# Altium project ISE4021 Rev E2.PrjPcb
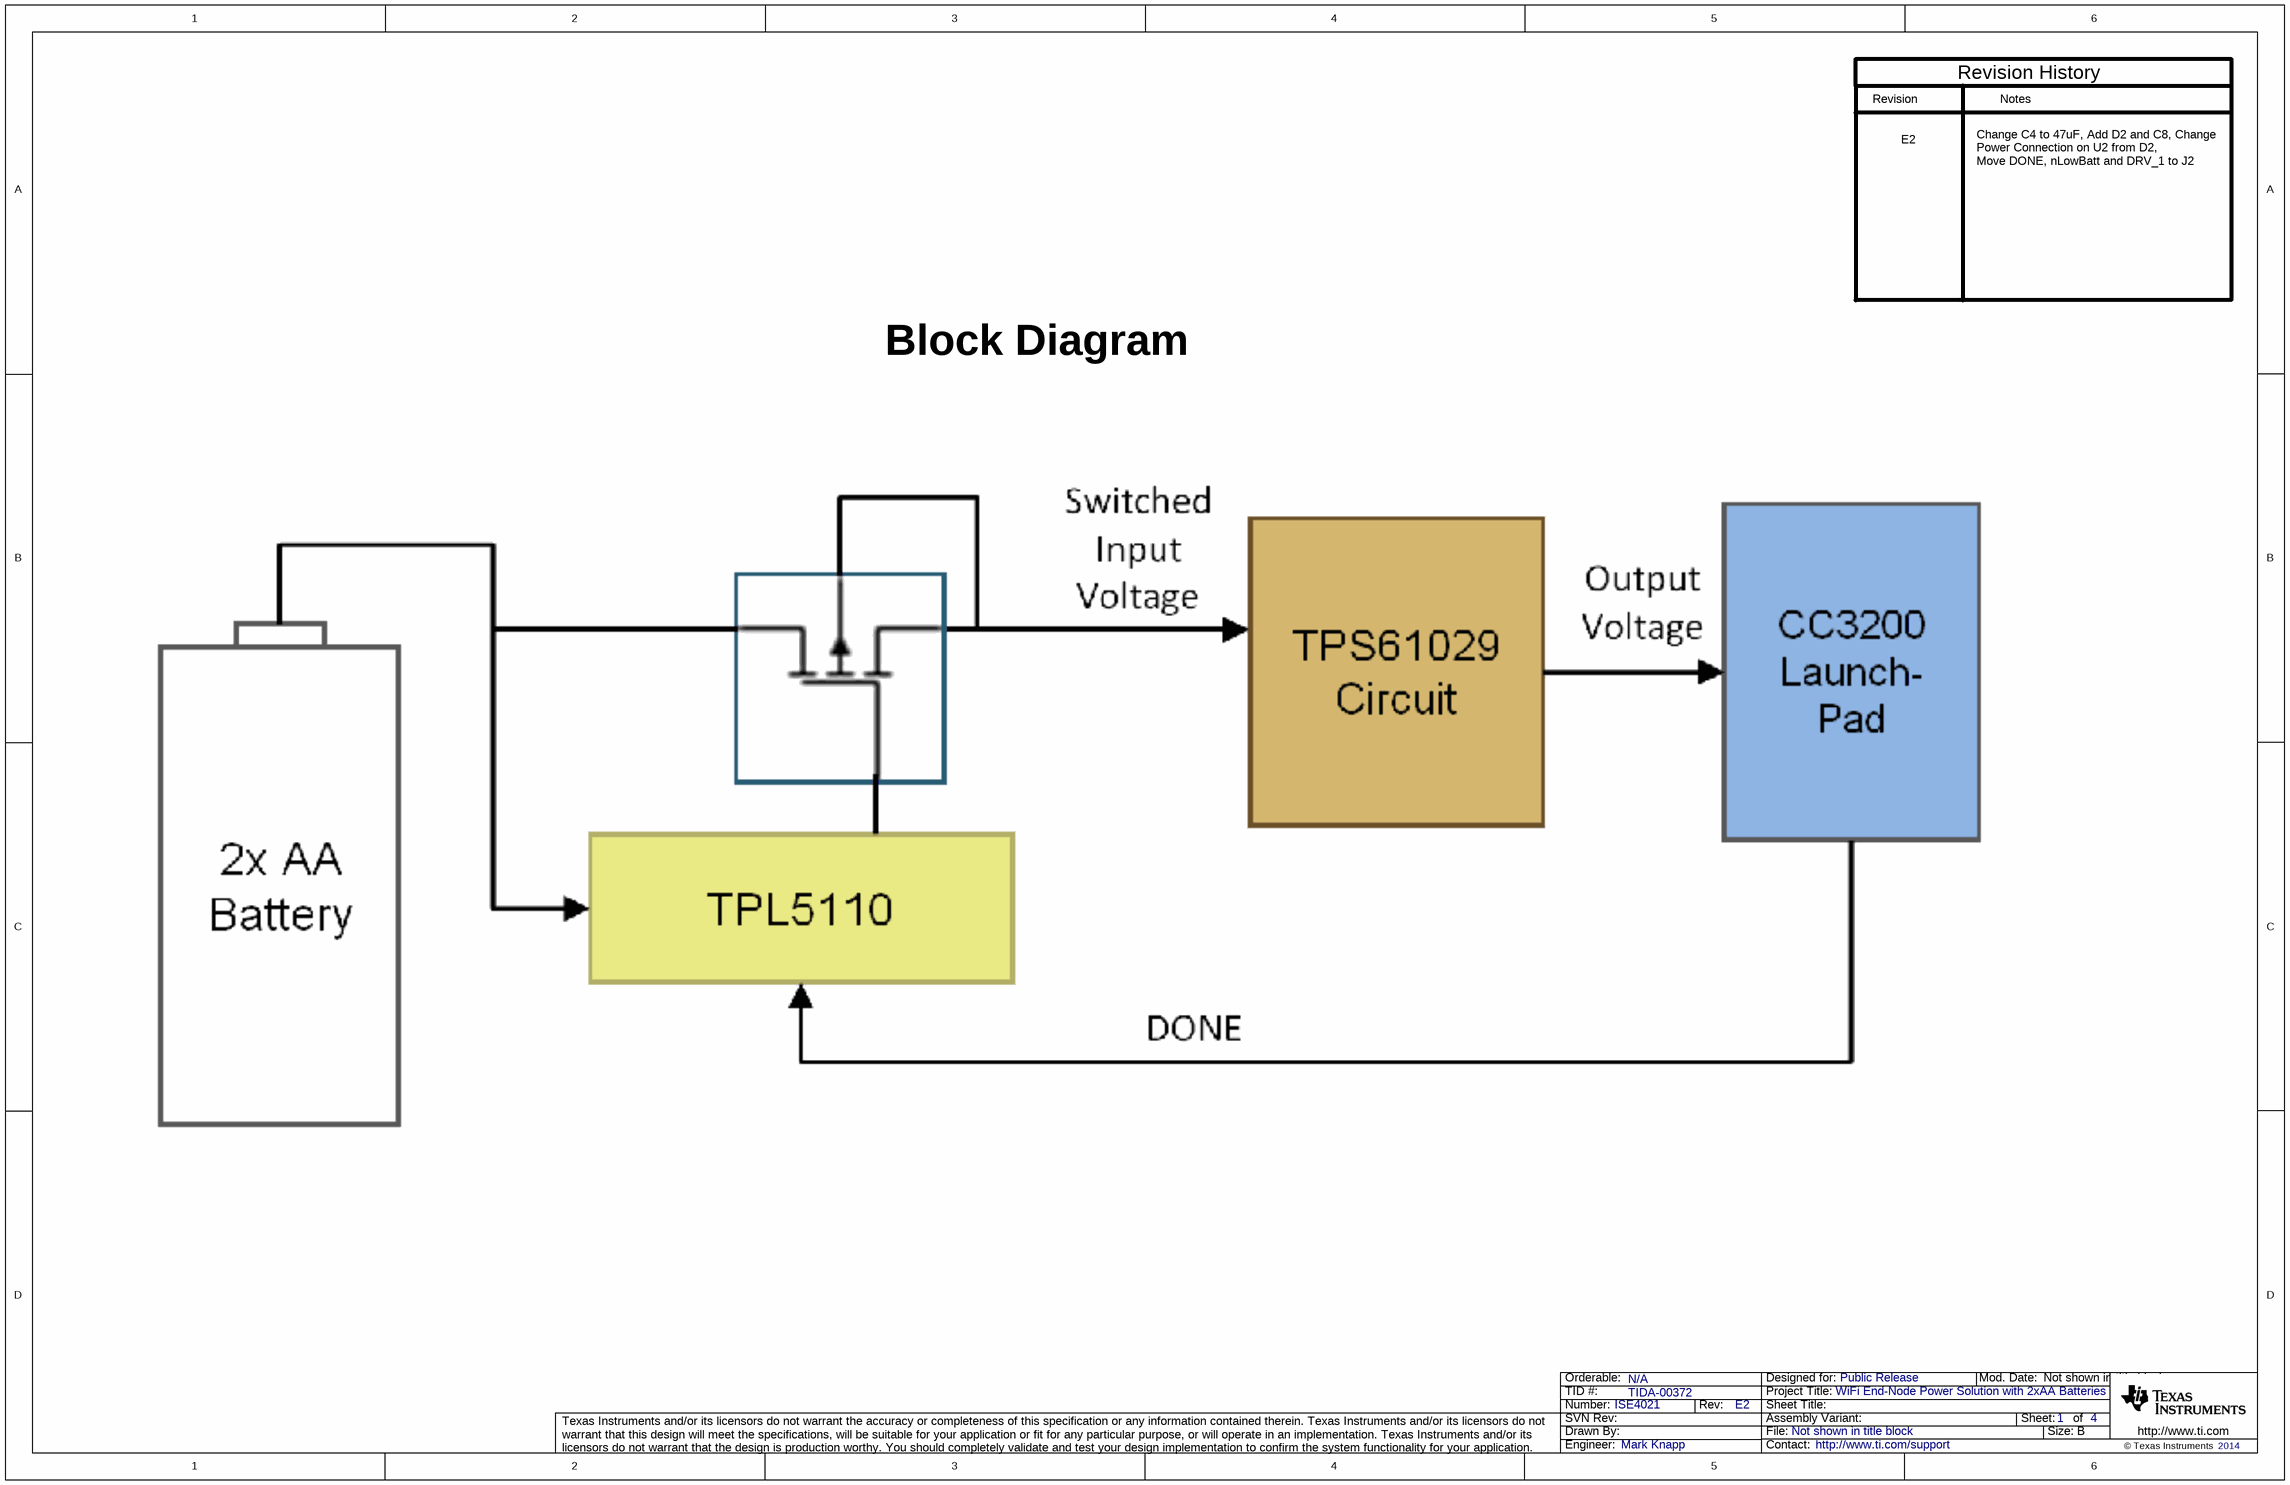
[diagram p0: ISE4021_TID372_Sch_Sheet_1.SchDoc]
TID: TIDA-00372; TechSupport: http://www.ti.com/support; SCH_Rev: E2; PRJ_Title: WiFi End-Node Power Solution with 2xAA Batteries; PRJ_Number: ISE4021; PRJ_Engineer: Mark Knapp; PRJ_Customer: Public Release; PCB_Rev: E2; PCB_Layout: Krypton Solutions LLC; EVM_Orderable: N/A; CopyrightYear: 2014
4 sheets, 58 parts. Net scope: global (net labels, ports and power ports of the same name join across sheets).
Board file: ISE4021_TID372_PCB.PcbDoc
Sheets:
  ISE4021_TID372_Sch_Sheet_1.SchDoc
  ISE4021_TID372_Sch_Sheet_2.SchDoc
  ISE4021_TID372_Sch_Sht_3.SchDoc
  ISE4021_TID372_Sch_Sheet_4.SchDoc

## Sheet ISE4021_TID372_Sch_Sheet_1.SchDoc
size 431 x 279 mm; Date: Not shown in title block; ApprovedBy: Not shown in title block; CheckedBy: Not shown in title block; Author: Not shown in title block; CompanyName: Not shown in title block; Engineer: Not shown in title block; Organization: Not shown in title block; Address1: Not shown in title block; Address2: Not shown in title block; Address3: Not shown in title block; Address4: Not shown in title block; DocumentNumber: 1; Revision: Use project parameter SCH_Rev; SheetNumber: 1; SheetTotal: 4; PageSetup: Record=PageOptions¦CenterHorizontal=True¦CenterVertical=True¦PrintScale=1.00¦XCorrection=1.00¦YCorrection=1.00¦PrintKind=0¦BorderSize=5000000¦LeftOffset=0¦BottomOffset=0¦Orientation=2¦PaperLength=1000¦PaperWidth=1000¦Scale=100¦PaperSource=15¦PrintQuality=600¦MediaType=1¦DitherType=10¦PaperKind=Letter¦PrintScaleMode=1

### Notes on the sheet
- Revision
- Notes
- Revision History
- E2
- Change C4 to 47uF, Add D2 and C8, Change Power Connection on U2 from D2,
  Move DONE, nLowBatt and DRV_1 to J2
- Block Diagram

## Sheet ISE4021_TID372_Sch_Sheet_2.SchDoc
size 431 x 279 mm; Date: Not shown in title block; ApprovedBy: Not shown in title block; CheckedBy: Not shown in title block; Author: Not shown in title block; CompanyName: Not shown in title block; Engineer: Not shown in title block; Organization: Not shown in title block; Address1: Not shown in title block; Address2: Not shown in title block; Address3: Not shown in title block; Address4: Not shown in title block; DocumentNumber: 2; Revision: Use project parameter SCH_Rev; SheetNumber: 2; SheetTotal: 4; PageSetup: Record=PageOptions¦CenterHorizontal=True¦CenterVertical=True¦PrintScale=0.96¦XCorrection=1.00¦YCorrection=1.00¦PrintKind=0¦BorderSize=5000000¦LeftOffset=0¦BottomOffset=0¦Orientation=2¦PaperLength=4318¦PaperWidth=2794¦Scale=100¦PaperSource=15¦PrintQuality=600¦MediaType=1¦DitherType=10¦PrintScaleMode=1¦PaperKind=Tabloid (11 x 17")¦PaperIndex=17
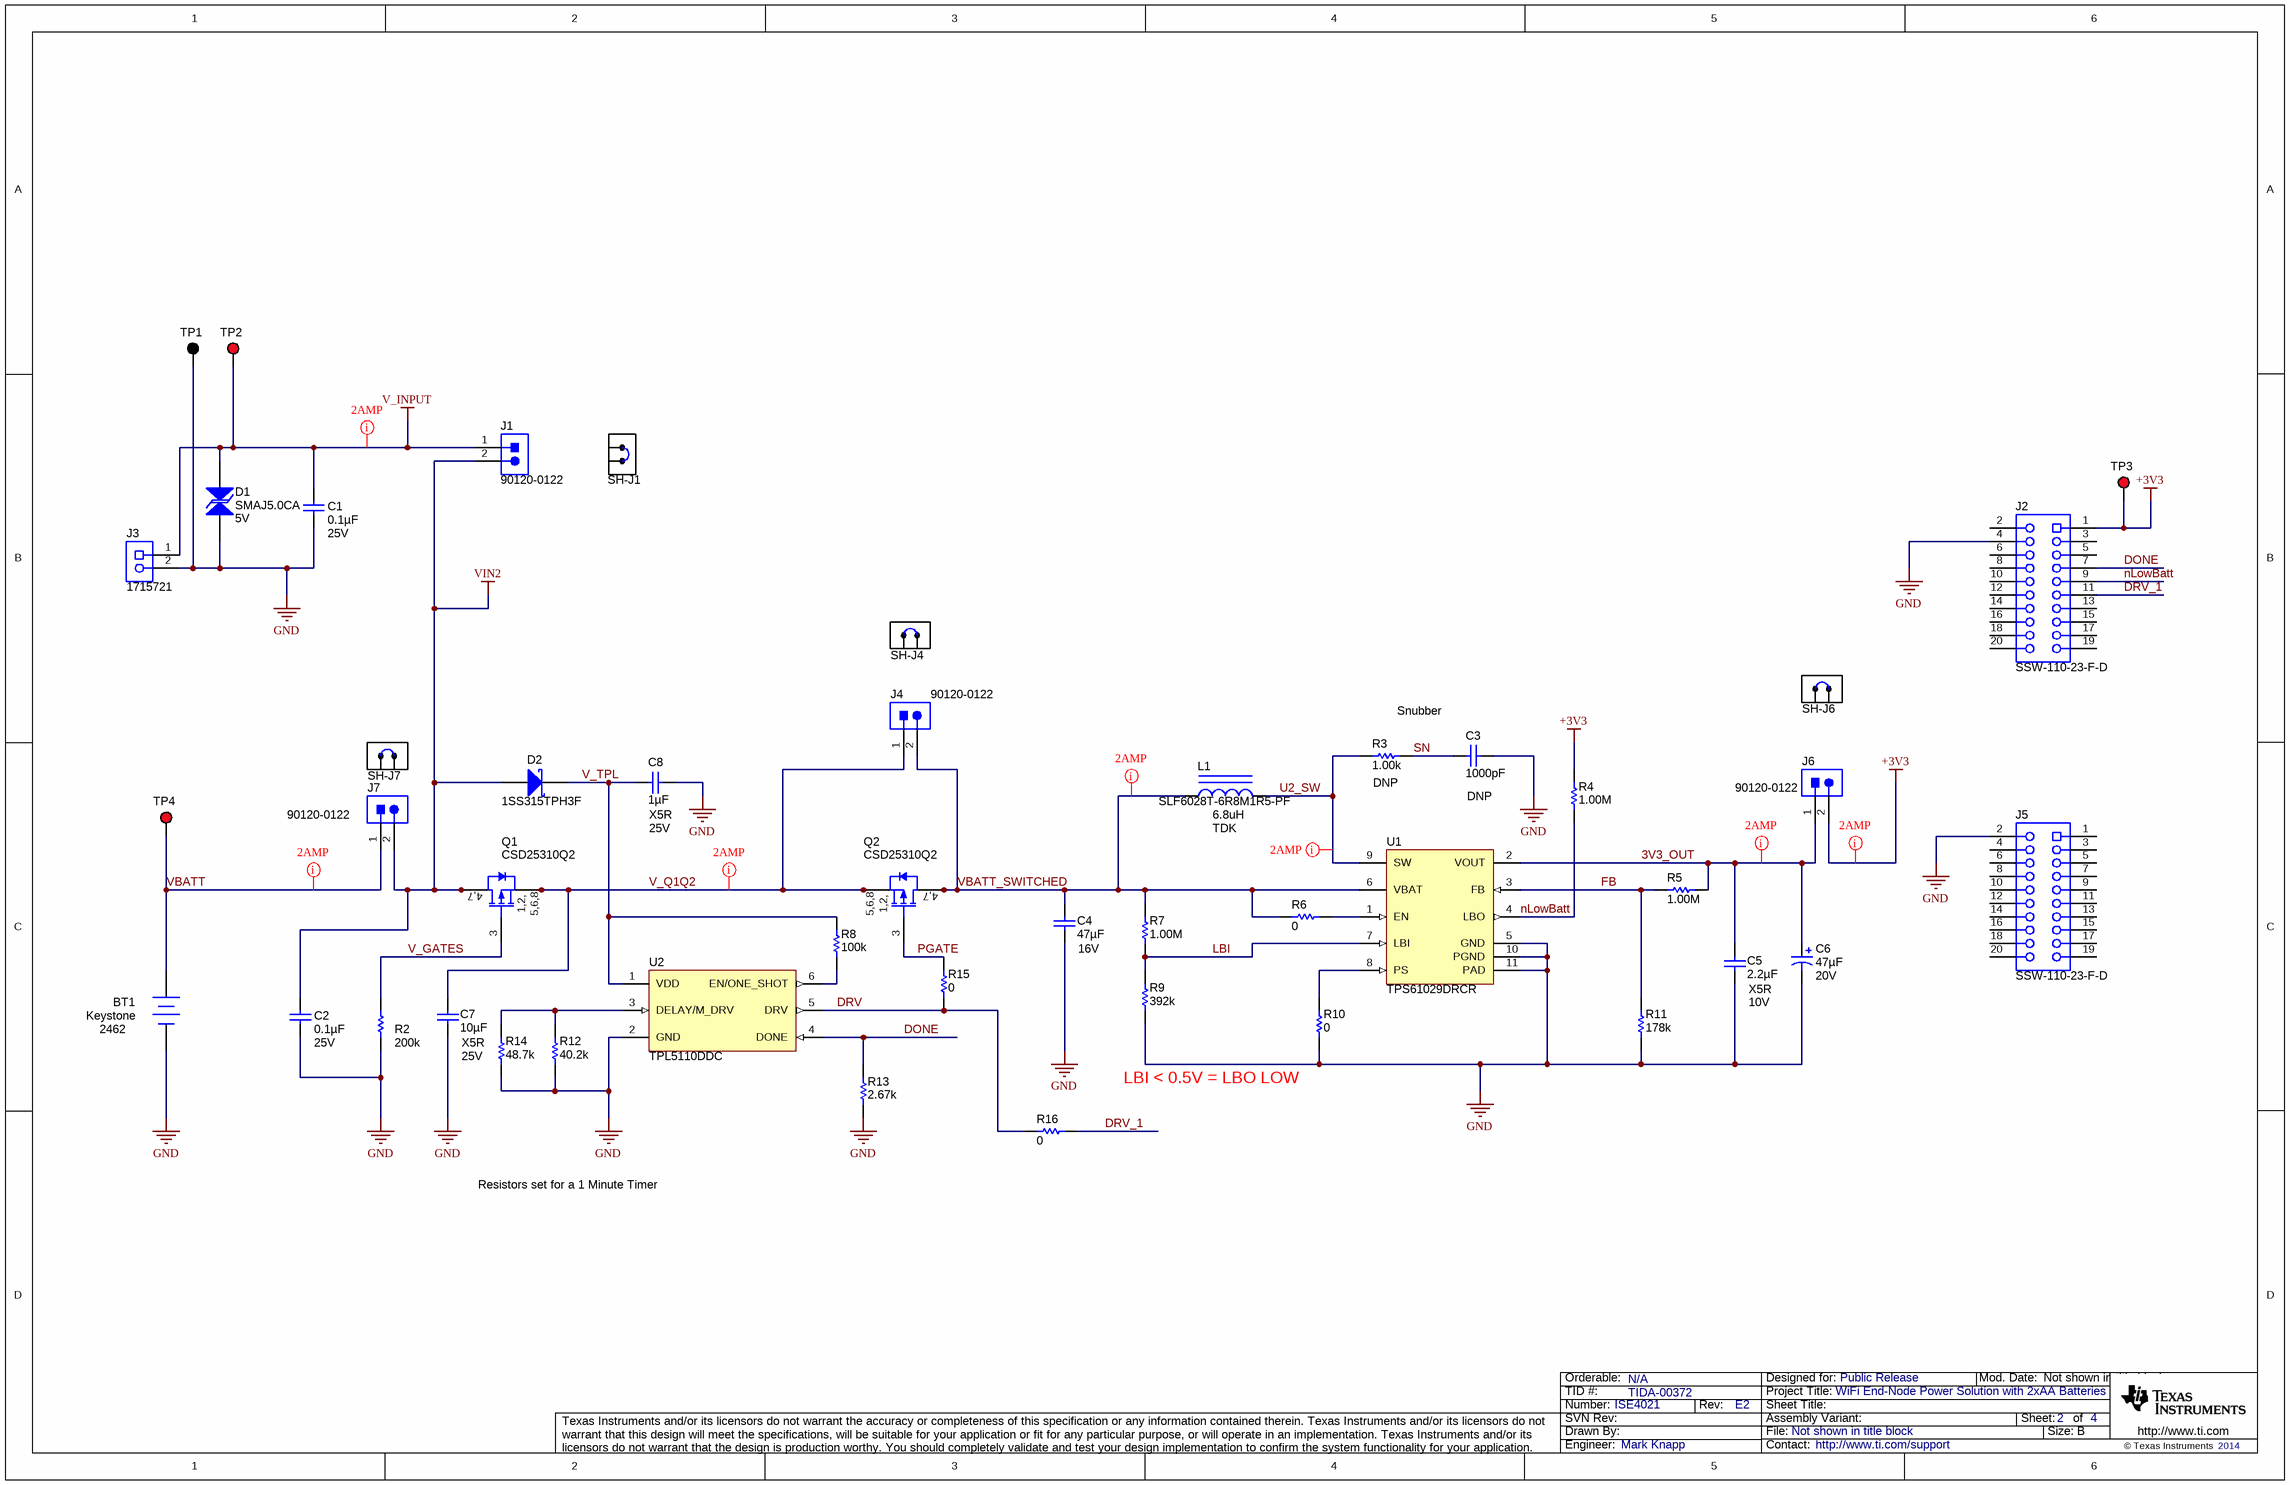
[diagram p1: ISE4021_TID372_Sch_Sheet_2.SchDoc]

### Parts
BT1  Manufacturer: Keystone  [Keystone_2462]  (hidden comment: 2462)
C1  ValueDisplayed: 0.1µF  Value2: 25V  [0603]  (hidden comment: 06033C104JAT2A)
C2  ValueDisplayed: 0.1µF  Value2: 25V  [0603]  (hidden comment: 06033C104JAT2A)
C3  ValueDisplayed: 1000pF  [0402]  (hidden comment: C1005C0G1E102J)
C4  ValueDisplayed: 47µF  Value2: 16V  [1210]  (hidden comment: GRM32ER61C476KE15L)
C5  ValueDisplayed: 2.2µF  Value2: 10V  TempCo: X5R  [0805_HV]  (hidden comment: C2012X5R1A225K/0.85)
C6  ValueDisplayed: 47µF  Value2: 20V  [7343-31]  (hidden comment: T495D476K020ATE100)
C7  ValueDisplayed: 10µF  Value2: 25V  TempCo: X5R  [0805_HV]  (hidden comment: C2012X5R1E106K125AB)
C8  ValueDisplayed: 1µF  Value2: 25V  TempCo: X5R  [0805_HV]  (hidden comment: GRM216R61E105KA12D)
D1  SMAJ5.0CA  value 5V  [SMA]
D2  1SS315TPH3F  [sod-323]
J1  90120-0122  [CONN_90120-0122]
J2  SSW-110-23-F-D  [CONN_SSW-110-23-F-D]
J3  1715721  [PhoenixContact_1715721]
J4  90120-0122  [CONN_90120-0122]
J5  SSW-110-23-F-D  [CONN_SSW-110-23-F-D]
J6  90120-0122  [CONN_90120-0122]
J7  90120-0122  [CONN_90120-0122]
L1  SLF6028T-6R8M1R5-PF  value 6.8uH  Manufacturer: TDK  [SLF6028]
Q1  CSD25310Q2  [TRANS_NexFET_Q2]
Q2  CSD25310Q2  [TRANS_NexFET_Q2]
R2  ValueDisplayed: 200k  [0402]  (hidden comment: CRCW0402200KFKED)
R3  ValueDisplayed: 1.00k  [0402]  (hidden comment: CRCW04021K00FKED)
R4  ValueDisplayed: 1.00M  [0603]  (hidden comment: CRCW06031M00FKEA)
R5  ValueDisplayed: 1.00M  [0603]  (hidden comment: CRCW06031M00FKEA)
R6  ValueDisplayed: 0  [0603]  (hidden comment: CRCW06030000Z0EA)
R7  ValueDisplayed: 1.00M  [0603]  (hidden comment: CRCW06031M00FKEA)
R8  ValueDisplayed: 100k  [0603]  (hidden comment: CRCW0603100KFKEA)
R9  ValueDisplayed: 392k  [0603]  (hidden comment: CRCW0603392KFKEA)
R10  ValueDisplayed: 0  [0603]  (hidden comment: CRCW06030000Z0EA)
R11  ValueDisplayed: 178k  [0603]  (hidden comment: CRCW0603178KFKEA)
R12  ValueDisplayed: 40.2k  [0603]  (hidden comment: CRCW060340K2FKEA)
R13  ValueDisplayed: 2.67k  [0603]  (hidden comment: CRCW06032K67FKEA)
R14  ValueDisplayed: 48.7k  [0603]  (hidden comment: CRCW060348K7FKEA)
R15  ValueDisplayed: 0  [0402]  (hidden comment: CRCW04020000Z0ED)
R16  ValueDisplayed: 0  [0402]  (hidden comment: CRCW04020000Z0ED)
SH-J1  2SN-BK-G  [2SN-BK-G]  (value not drawn)
SH-J4  2SN-BK-G  [2SN-BK-G]  (value not drawn)
SH-J6  2SN-BK-G  [2SN-BK-G]  (value not drawn)
SH-J7  2SN-BK-G  [2SN-BK-G]  (value not drawn)
TP1  5001  [Keystone5001]  (value not drawn)
TP2  5000  [Keystone5000]  (value not drawn)
TP3  5000  [Keystone5000]  (value not drawn)
TP4  5000  [Keystone5000]  (value not drawn)
U1  TPS61029DRCR  [DRC0010A]
U2  TPL5110DDC  [DDC0006A_N]

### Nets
+3V3: J2.1 J6.2 R4.2 TP3.1
GND: BT1.2(-) C1.2 C2.2 C3.2 C4.2 C5.2 C6.2(-) C7.2 C8.1 D1.2 J2.4 J3.2 J5.2 R2.1 R9.1 R10.1 R11.1 R12.1 R13.1 R14.1 TP1.1 U1.5(GND) U1.10(PGND) U1.11(PAD) U2.2(GND)
V_INPUT: C1.1 D1.1 J1.1 J3.1 TP2.1
VIN2: C2.1 D2.2(A) J1.2 J7.2 Q1.4(D) Q1.7(D)
3V3_OUT: C5.1 C6.1(+) J6.1 R5.2 U1.2(VOUT)
DONE: J2.7 R13.2 U2.4(DONE)
DRV: R15.1 R16.2 U2.5(DRV)
DRV_1: J2.11 R16.1
FB: R5.1 R11.2 U1.3(FB)
LBI: R7.1 R9.2 U1.7(LBI)
nLowBatt: J2.9 R4.1 U1.4(LBO)
PGATE: Q2.3(G) R15.2
SN: C3.1 R3.1
U2_SW: L1.2 R3.2 U1.9(SW)
V_GATES: Q1.3(G) R2.2
V_Q1Q2: C7.1 J4.1 Q1.1(S) Q1.2(S) Q1.5(S) Q1.6(S) Q1.8(S) Q2.1(S) Q2.2(S) Q2.5(S) Q2.6(S) Q2.8(S)
V_TPL: C8.2 D2.1(K) R8.2 U2.1(VDD)
VBATT: BT1.1(+) J7.1 TP4.1
VBATT_SWITCHED: C4.1 J4.2 L1.1 Q2.4(D) Q2.7(D) R6.1 R7.2 U1.6(VBAT)
NetR6_2: R6.2 U1.1(EN)
NetR8_1: R8.1 U2.6(EN/ONE_SHOT)
NetR10_2: R10.2 U1.8(PS)
NetR12_2: R12.2 R14.2 U2.3(DELAY/M_DRV)

Not connected (* = marked no-connect by the designer): J2 2 3 5 6 8 10 12 13 14 15 16 17 18 19 20; J5 1 3 4 5 6 7 8 9 10 11 12 13 14 15 16 17 18 19 20

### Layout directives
2AMP: 2AMP: 3V3_OUT, +3V3, U2_SW, V_INPUT, V_Q1Q2, VBATT, VBATT_SWITCHED

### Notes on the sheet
- Snubber
- (near R3) DNP
- (near C3) DNP
- LBI < 0.5V = LBO LOW
- Resistors set for a 1 Minute Timer

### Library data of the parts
BT1 = 2462: 2x AA Battery Holder, Through-hole mount
C1 C2 = 06033C104JAT2A: CAP, CERM, 0.1 µF, 25 V, +/- 5%, X7R, 0603; Manufacturer: AVX; Polarized: N; CompType: Capacitor; Value: 0.1uF; U/M: EA; Cap_F: 0.0000001; Tolerance_%: 5; ESR_ohm: 0.05; Value1: 0.05 ohm; VDC_V: 25; TaMin_C: -55; TaMax_C: 125
C3 = C1005C0G1E102J: CAP, CERM, 1000 pF, 25 V, +/- 5%, C0G/NP0, 0402; Manufacturer: TDK; Polarized: N; CompType: Capacitor; Value: 1000pF; U/M: EA; Cap_F: 0.000000001; Tolerance_%: 5; Value1: Unknown; VDC_V: 25; Value2: 25V; TaMin_C: -55; TaMax_C: 125
C4 = GRM32ER61C476KE15L: CAP, CERM, 47 µF, 16 V, +/- 10%, X5R, 1210; Manufacturer: MuRata; Polarized: N; CompType: Capacitor; Value: 47uF; U/M: EA; Cap_F: 0.000047; Tolerance_%: 10; Value1: Unknown; VDC_V: 16; TaMin_C: -55; TaMax_C: 85
C5 = C2012X5R1A225K/0.85: CAP, CERM, 2.2 µF, 10 V, +/- 10%, X5R, 0805; Manufacturer: TDK; Polarized: N; CompType: Capacitor; Value: 2.2uF; U/M: EA; Cap_F: 0.0000022; Tolerance_%: 10; ESR_ohm: 0.0049; Value1: 0.0049 ohm; IRMS_A: 2.08; TaMin_C: -55; TaMax_C: 85; Cap_Case: 0805
C6 = T495D476K020ATE100: CAP, TA, 47 µF, 20 V, +/- 10%, 0.1 ohm, SMD; Manufacturer: Kemet; Polarized: Y; CompType: Capacitor; Value: 47uF; U/M: EA; Cap_F: 0.000047; Tolerance_%: 10; Value1: 0.1 ohm; VDC_V: 20; ESR_ohm: 0.1; IRMS_A: 1.102; TaMin_C: -55; TaMax_C: 125; Cap_Case: D
C7 = C2012X5R1E106K125AB: CAP, CERM, 10 µF, 25 V, +/- 10%, X5R, 0805; Manufacturer: TDK; Polarized: N; CompType: Capacitor; Value: 10uF; U/M: EA; Cap_F: 0.00001; Tolerance_%: 10; Value1: Unknown; VDC_V: 25; TaMin_C: -55; TaMax_C: 85; Cap_Case: 0805
C8 = GRM216R61E105KA12D: CAP, CERM, 1 µF, 25 V, +/- 10%, X5R, 0805; Manufacturer: MuRata; Polarized: N; CompType: Capacitor; Value: 1uF; U/M: EA; Cap_F: 0.000001; Tolerance_%: 10; ESR_ohm: 0.009; Value1: 0.009 ohm; VDC_V: 25; TaMin_C: -55; TaMax_C: 85; Cap_Case: 0805
D1 = SMAJ5.0CA: Diode, TVS, Bi, 5 V, 400 W, SMA; Manufacturer: Littelfuse; U/M: EA; Power_W: 400; Vr_V: 5; Value1: 400W; RJA_CperW: 120
D2 = 1SS315TPH3F: Diode, Schottky, 5 V, 0.03 A, SOD-323; Manufacturer: Toshiba; U/M: EA; Vf_V: 0.38; Value: 5V; Value1: 0.03A; Value2: 0.38V; Io_A: 0.03; Vr_V: 5; TJmax_C: 125
J1 J4 J6 J7 = 90120-0122: Header, 100mil, 2x1, Tin, TH; Manufacturer: Molex; SymbolCreator: a0412235; U/M: EA
J2 J5 = SSW-110-23-F-D: Connector, Receptacle, 100mil, 10x2, Gold plated, TH; Manufacturer: Samtec; SymbolCreator: a0412235; U/M: EA
J3 = 1715721: Conn Term Block, 2POS, 5.08mm, TH; Manufacturer: Phoenix Contact; SymbolCreator: a0412235; Value: 2x1; CompType: Terminal Block; U/M: EA
L1 = SLF6028T-6R8M1R5-PF: Inductor, Shielded Drum Core, Ferrite, 6.8 µH, 1.5 A, 0.0354 ohm, SMD; Ind_H: 6.8E-6; ValueDisplayed: 6.8µH; Imax_A: 1.5; Irms: 2.2A @ 25C rise; Isat: 1.5A @ 30% inductance drop; DCR_ohm: 0.0354; Value2: 1.5A
Q1 Q2 = CSD25310Q2: MOSFET, P-CH, -20 V, -20 A, SON 2x2mm; Manufacturer: Texas Instruments; Alternate Manufacturer: None; SymbolCreator: a0411947; U/M: EA; ChType: P; Value: -20V; Value1: 0.0239 ohm; Rdson45_ohm: 0.0239; Value2: 3.6 nC; QgTyp_nC: 3.6; Vgs_V: 8
R2 = CRCW0402200KFKED: RES, 200 k, 1%, 0.063 W, 0402; Manufacturer: Vishay-Dale; CompType: Resistor; Res_ohm: 200000; Value: 200k; Tolerance_%: 1; Power_W: 0.063; Value2: 0.063W; VDC_V: 50; TempCo: 100 ppm/C; EIA_Code: E96; U/M: EA
R3 = CRCW04021K00FKED: RES, 1.00 k, 1%, 0.063 W, 0402; Manufacturer: Vishay-Dale; CompType: Resistor; Value: 1.00k; Res_ohm: 1000; Value_Code: 1k00; Tolerance_%: 1; Power_W: 0.063; Value2: 0.063W; VDC_V: 50; TempCo: 100 ppm/C; EIA_Code: E96; U/M: EA
R4 R5 R7 = CRCW06031M00FKEA: RES, 1.00 M, 1%, 0.1 W, 0603; Manufacturer: Vishay-Dale; CompType: Resistor; Value: 1.00Meg; Res_ohm: 1000000; Value_Code: 1M00; Tolerance_%: 1; Power_W: 0.1; Value2: 0.1W; VDC_V: 75; TempCo: 100 ppm/C; EIA_Code: E96; U/M: EA
R6 R10 = CRCW06030000Z0EA: RES, 0, 5%, 0.1 W, 0603; Manufacturer: Vishay-Dale; CompType: Resistor; Value: 0; Value_Code: 0000; Tolerance_%: 5; Power_W: 0.1; Value2: 0.1W; VDC_V: 75; TempCo: 200 ppm/C; EIA_Code: E24; U/M: EA
R8 = CRCW0603100KFKEA: RES, 100 k, 1%, 0.1 W, 0603; Manufacturer: Vishay-Dale; CompType: Resistor; Value: 100k; Res_ohm: 100000; Tolerance_%: 1; Power_W: 0.1; Value2: 0.1W; VDC_V: 75; TempCo: 100 ppm/C; EIA_Code: E96; U/M: EA
R9 = CRCW0603392KFKEA: RES, 392 k, 1%, 0.1 W, 0603; Manufacturer: Vishay-Dale; CompType: Resistor; Value: 392k; Res_ohm: 392000; Tolerance_%: 1; Power_W: 0.1; Value2: 0.1W; VDC_V: 75; TempCo: 100 ppm/C; EIA_Code: E96; U/M: EA
R11 = CRCW0603178KFKEA: RES, 178 k, 1%, 0.1 W, 0603; Manufacturer: Vishay-Dale; CompType: Resistor; Value: 178k; Res_ohm: 178000; Tolerance_%: 1; Power_W: 0.1; Value2: 0.1W; VDC_V: 75; TempCo: 100 ppm/C; EIA_Code: E96; U/M: EA
R12 = CRCW060340K2FKEA: RES, 40.2 k, 1%, 0.1 W, 0603; Manufacturer: Vishay-Dale; CompType: Resistor; Value: 40.2k; Res_ohm: 40200; Value_Code: 40k2; Tolerance_%: 1; Power_W: 0.1; Value2: 0.1W; VDC_V: 75; TempCo: 100 ppm/C; EIA_Code: E96; U/M: EA
R13 = CRCW06032K67FKEA: RES, 2.67 k, 1%, 0.1 W, 0603; Manufacturer: Vishay-Dale; CompType: Resistor; Value: 2.67k; Res_ohm: 2670; Value_Code: 2k67; Tolerance_%: 1; Power_W: 0.1; Value2: 0.1W; VDC_V: 75; TempCo: 100 ppm/C; EIA_Code: E96; U/M: EA
R14 = CRCW060348K7FKEA: RES, 48.7 k, 1%, 0.1 W, 0603; Manufacturer: Vishay-Dale; CompType: Resistor; Value: 48.7k; Res_ohm: 48700; Value_Code: 48k7; Tolerance_%: 1; Power_W: 0.1; Value2: 0.1W; VDC_V: 75; TempCo: 100 ppm/C; EIA_Code: E96; U/M: EA
R15 R16 = CRCW04020000Z0ED: RES, 0, 5%, 0.063 W, 0402; Manufacturer: Vishay-Dale; CompType: Resistor; Value: 0; Value_Code: 0000; Tolerance_%: 5; Power_W: 0.063; Value2: 0.063W; VDC_V: 50; TempCo: 200 ppm/C; EIA_Code: E24; U/M: EA
SH-J1 SH-J4 SH-J6 SH-J7 = 2SN-BK-G: Shunt, 2mm, Gold plated, Black; Manufacturer: Samtec; Value: 1x2; Note: You can "mate" this to a header by matching the designator.  i.e. use SH-J3 for header J3
TP1 = 5001: Test Point, Miniature, Black, TH; Manufacturer: Keystone; CompType: Test Point Loop; U/M: EA
TP2-TP4 = 5000: Test Point, Miniature, Red, TH; Manufacturer: Keystone; CompType: Test Point Loop; U/M: EA
U1 = TPS61029DRCR: Adjustable, 1.8-A Switch, 96% Efficient Boost Converter with Down-Mode, DRC0010A; Alternate PartNumber: TPS61029DRCT; Manufacturer: Texas Instruments; SymbolCreator: Altium; CompType: IC; U/M: EA
U2 = TPL5110DDC: Ultra-Low Power System Timer with MOS driver and manual MSFET power ON, DDC0006A; Manufacturer: Texas Instruments; SymbolCreator: a0411947; CompType: IC; U/M: EA

## Sheet ISE4021_TID372_Sch_Sht_3.SchDoc
size 431 x 279 mm; Date: Not shown in title block; ApprovedBy: Not shown in title block; CheckedBy: Not shown in title block; Author: Not shown in title block; CompanyName: Not shown in title block; Engineer: Not shown in title block; Organization: Not shown in title block; Address1: Not shown in title block; Address2: Not shown in title block; Address3: Not shown in title block; Address4: Not shown in title block; DocumentNumber: 3; Revision: Use project parameter SCH_Rev; SheetNumber: 3; SheetTotal: 4; PageSetup: Record=PageOptions¦CenterHorizontal=True¦CenterVertical=True¦PrintScale=1.00¦XCorrection=1.00¦YCorrection=1.00¦PrintKind=0¦BorderSize=5000000¦LeftOffset=0¦BottomOffset=0¦Orientation=2¦PaperLength=1000¦PaperWidth=1000¦Scale=100¦PaperSource=15¦PrintQuality=600¦MediaType=1¦DitherType=10¦PaperKind=Letter¦PrintScaleMode=1
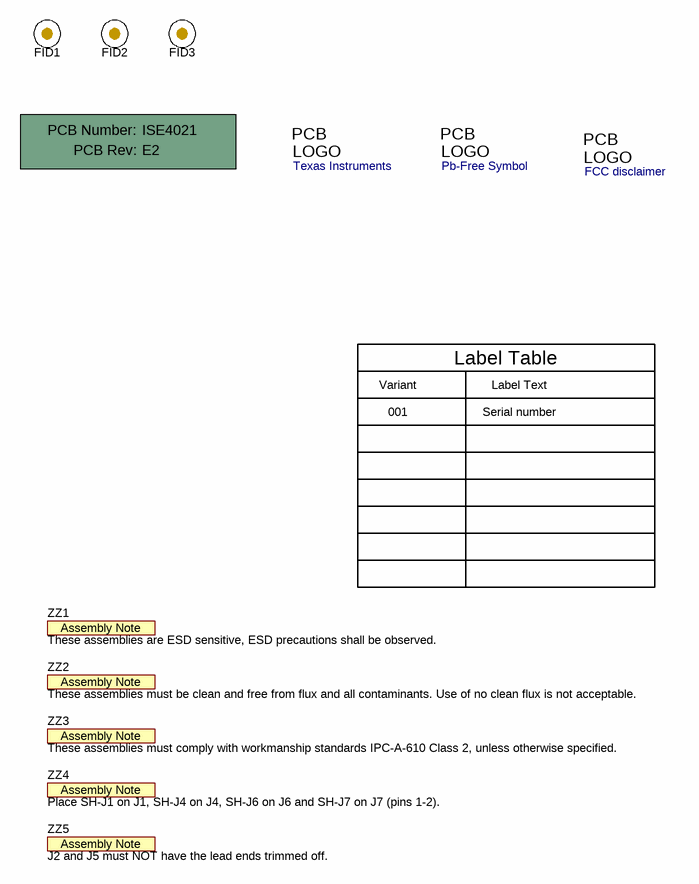
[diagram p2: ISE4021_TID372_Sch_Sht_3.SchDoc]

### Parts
!PCB1  Printed Circuit Board  (value not drawn)  (mechanical)
FID1  Fiducial  [Fiducial10-20]  (value not drawn)
FID2  Fiducial  [Fiducial10-20]  (value not drawn)
FID3  Fiducial  [Fiducial10-20]  (value not drawn)
Logo1  Texas Instruments  [TI_Stacked_Overlay_Small]  (no BOM)
Logo2  Pb-Free Symbol  [Pb-Free_Overlay_Small]  (no BOM)
Logo3  FCC disclaimer  [FCC_disclaimer]  (no BOM)
ZZ1  These assemblies are ESD sensitive, ESD precautions shall be observed.  [AssemblyNote]  (no BOM)
ZZ2  These assemblies must be clean and free from flux and all contaminants. Use of no clean flux is not acceptable.  [AssemblyNote]  (no BOM)
ZZ3  These assemblies must comply with workmanship standards IPC-A-610 Class 2, unless otherwise specified.  [AssemblyNote]  (no BOM)
ZZ4  Place SH-J1 on J1, SH-J4 on J4, SH-J6 on J6 and SH-J7 on J7 (pins 1-2).  [AssemblyNote]  (no BOM)
ZZ5  J2 and J5 must NOT have the lead ends trimmed off.  [AssemblyNote]  (no BOM)

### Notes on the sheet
- Variant
- Label Table
- Label Text
- 001
- Serial number

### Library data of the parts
!PCB1 = PCB: Manufacturer: Any; PartNumber: ISE4021; SymbolCreator: a0412235
FID1-FID3 = Fiducial: Fiducial mark.  There is nothing to buy or mount.; SymbolCreator: codlsc
Logo1 = TI_Logo: Texas Instrument Corporate Signature; SymbolCreator: a0412235
Logo2 = Pb-Free: SymbolCreator: a0412235
Logo3 = FCC_disclaimer: SymbolCreator: codlsc
ZZ1-ZZ5 = AssemblyNote: SymbolCreator: codlsc

## Sheet ISE4021_TID372_Sch_Sheet_4.SchDoc
size 431 x 279 mm; Date: Not shown in title block; ApprovedBy: Not shown in title block; CheckedBy: Not shown in title block; Author: Not shown in title block; CompanyName: Not shown in title block; Engineer: Not shown in title block; Organization: Not shown in title block; Address1: Not shown in title block; Address2: Not shown in title block; Address3: Not shown in title block; Address4: Not shown in title block; DocumentNumber: 4; Revision: Use project parameter SCH_Rev; SheetNumber: 4; SheetTotal: 4; PageSetup: Record=PageOptions¦CenterHorizontal=True¦CenterVertical=True¦PrintScale=1.00¦XCorrection=1.00¦YCorrection=1.00¦PrintKind=0¦BorderSize=5000000¦LeftOffset=0¦BottomOffset=0¦Orientation=2¦PaperLength=1000¦PaperWidth=1000¦Scale=100¦PaperSource=15¦PrintQuality=600¦MediaType=1¦DitherType=10¦PaperKind=Letter¦PrintScaleMode=1
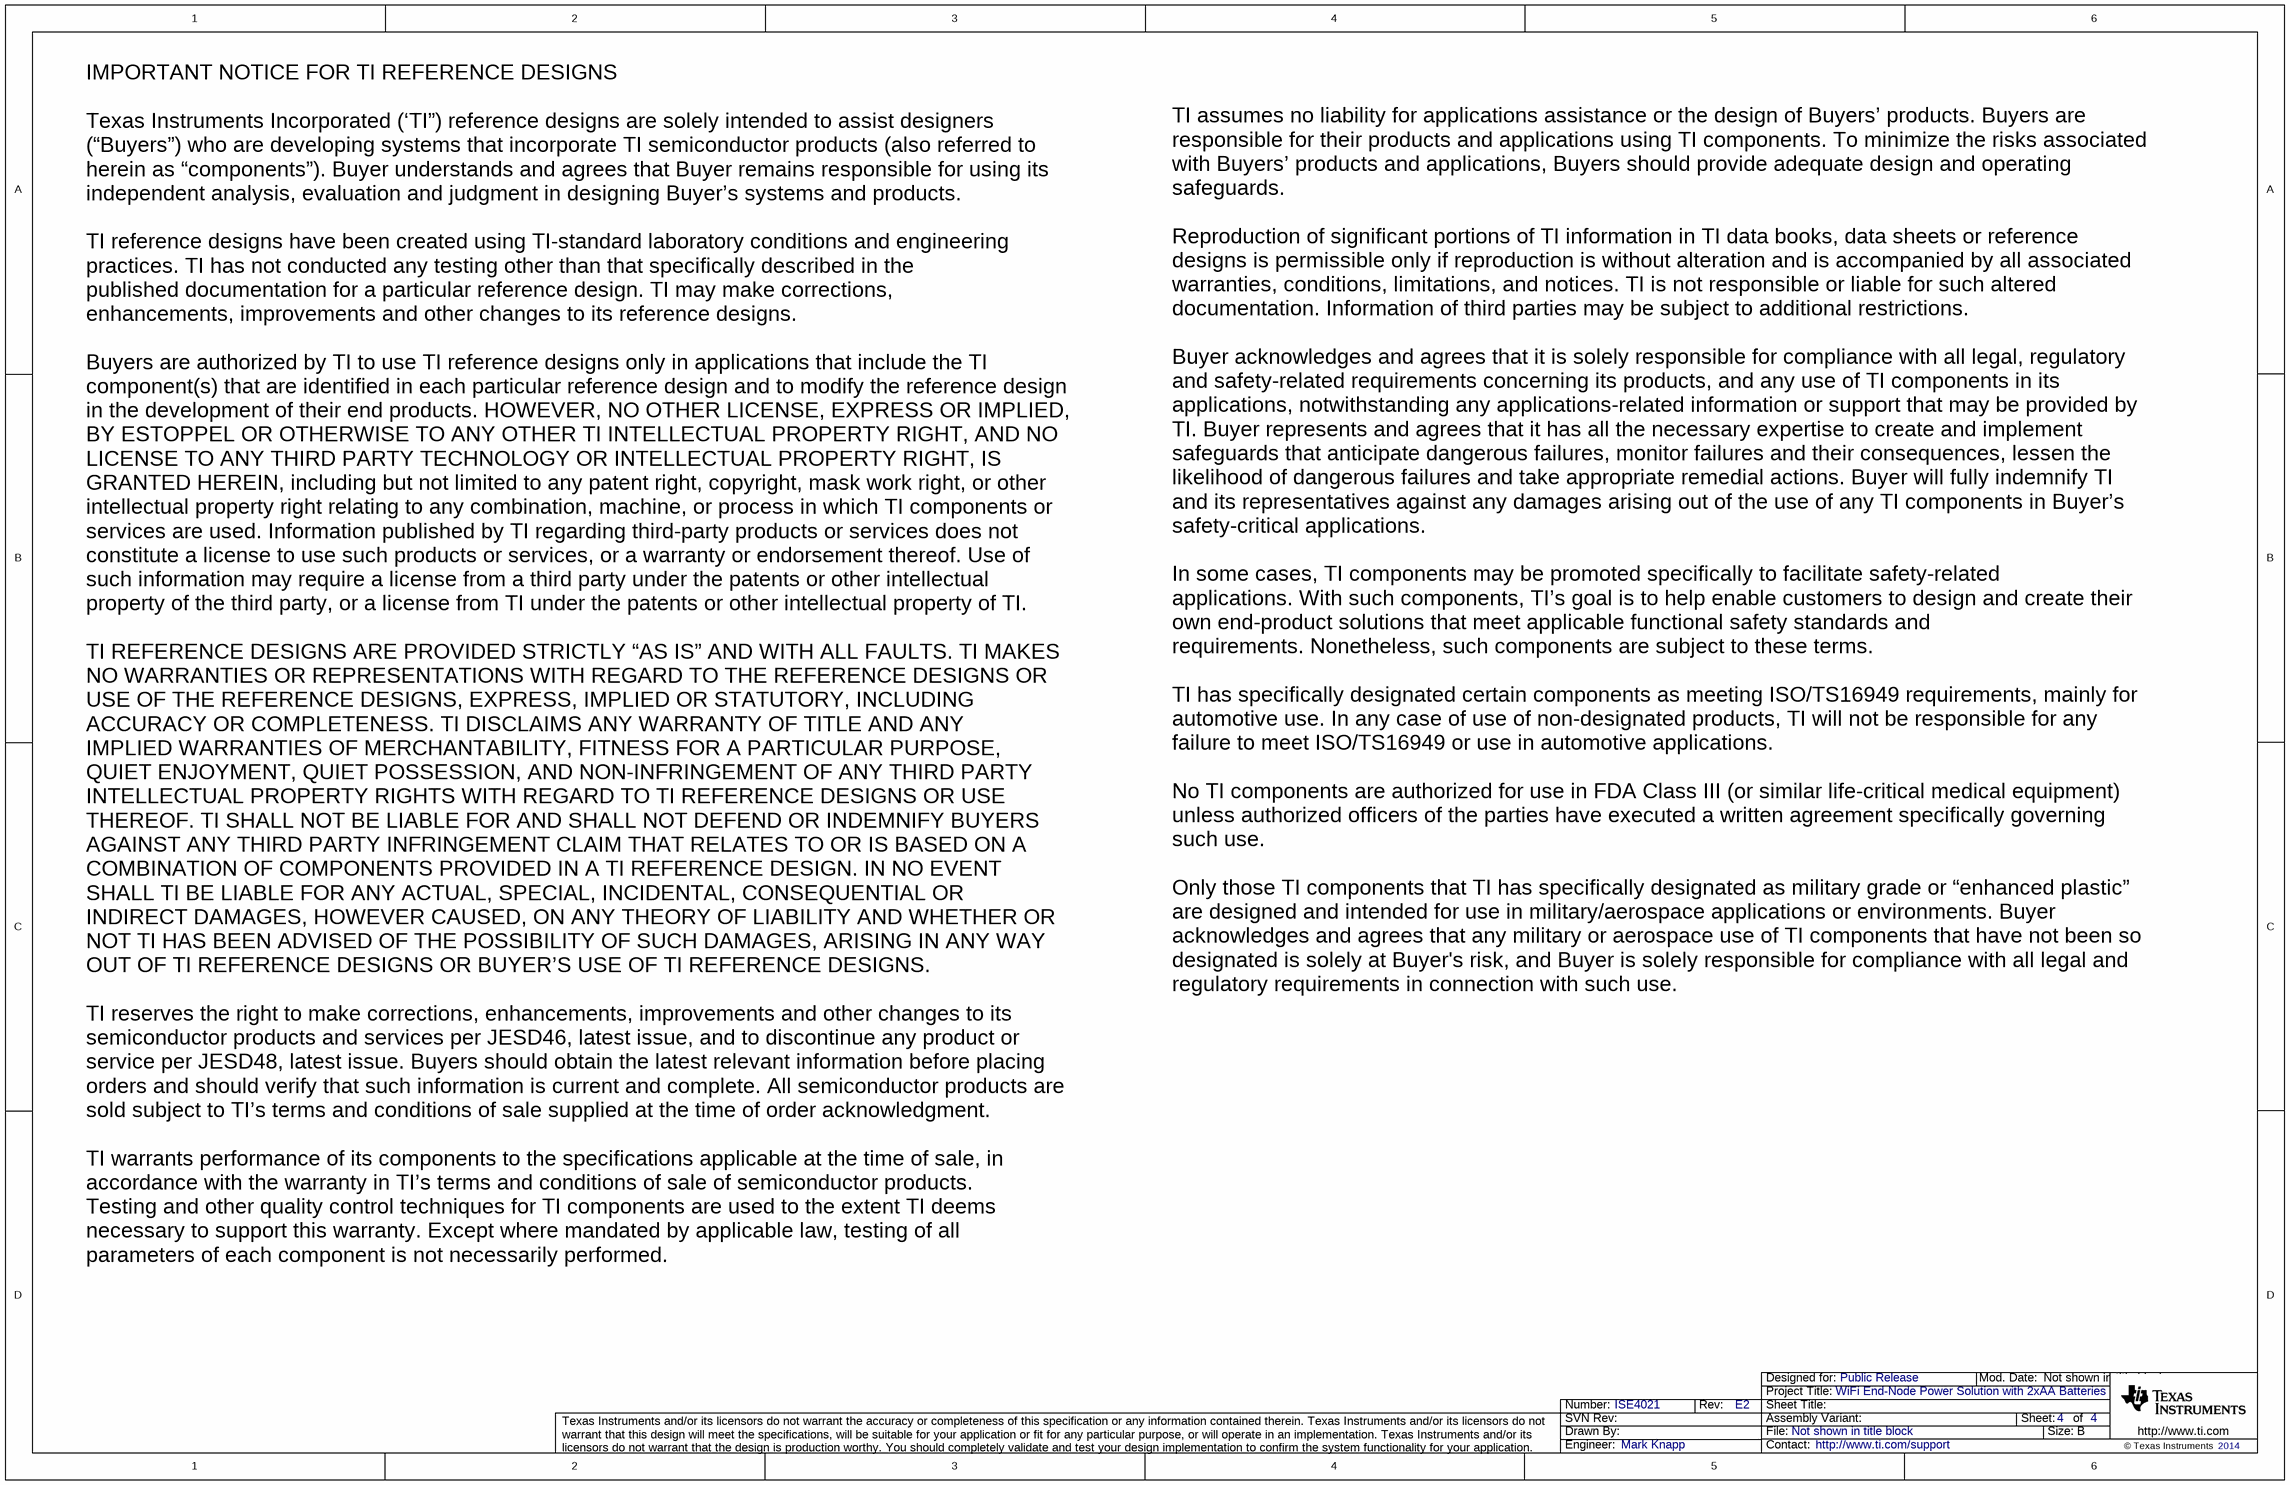
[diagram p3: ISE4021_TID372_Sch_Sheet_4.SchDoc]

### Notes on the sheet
- IMPORTANT NOTICE FOR TI REFERENCE DESIGNS
  Texas Instruments Incorporated (‘TI”) reference designs are solely intended to assist designers
  (“Buyers”) who are developing systems that incorporate TI semiconductor products (also referred to
  herein as “components”). Buyer understands and agrees that Buyer remains responsible for using its
  independent analysis, evaluation and judgment in designing Buyer’s systems and products.
  TI reference designs have been created using TI-standard laboratory conditions and engineering
  practices. TI has not conducted any testing other than that specifically described in the
  published documentation for a particular reference design. TI may make corrections,
  enhancements, improvements and other changes to its reference designs.
  Buyers are authorized by TI to use TI reference designs only in applications that include the TI
  component(s) that are identified in each particular reference design and to modify the reference design
  in the development of their end products. HOWEVER, NO OTHER LICENSE, EXPRESS OR IMPLIED,
  BY ESTOPPEL OR OTHERWISE TO ANY OTHER TI INTELLECTUAL PROPERTY RIGHT, AND NO
  LICENSE TO ANY THIRD PARTY TECHNOLOGY OR INTELLECTUAL PROPERTY RIGHT, IS
  GRANTED HEREIN, including but not limited to any patent right, copyright, mask work right, or other
  intellectual property right relating to any combination, machine, or process in which TI components or
  services are used. Information published by TI regarding third-party products or services does not
  constitute a license to use such products or services, or a warranty or endorsement thereof. Use of
  such information may require a license from a third party under the patents or other intellectual
  property of the third party, or a license from TI under the patents or other intellectual property of TI.
  TI REFERENCE DESIGNS ARE PROVIDED STRICTLY “AS IS” AND WITH ALL FAULTS. TI MAKES
  NO WARRANTIES OR REPRESENTATIONS WITH REGARD TO THE REFERENCE DESIGNS OR
  USE OF THE REFERENCE DESIGNS, EXPRESS, IMPLIED OR STATUTORY, INCLUDING
  ACCURACY OR COMPLETENESS. TI DISCLAIMS ANY WARRANTY OF TITLE AND ANY
  IMPLIED WARRANTIES OF MERCHANTABILITY, FITNESS FOR A PARTICULAR PURPOSE,
  QUIET ENJOYMENT, QUIET POSSESSION, AND NON-INFRINGEMENT OF ANY THIRD PARTY
  INTELLECTUAL PROPERTY RIGHTS WITH REGARD TO TI REFERENCE DESIGNS OR USE
  THEREOF. TI SHALL NOT BE LIABLE FOR AND SHALL NOT DEFEND OR INDEMNIFY BUYERS
  AGAINST ANY THIRD PARTY INFRINGEMENT CLAIM THAT RELATES TO OR IS BASED ON A
  COMBINATION OF COMPONENTS PROVIDED IN A TI REFERENCE DESIGN. IN NO EVENT
  SHALL TI BE LIABLE FOR ANY ACTUAL, SPECIAL, INCIDENTAL, CONSEQUENTIAL OR
  INDIRECT DAMAGES, HOWEVER CAUSED, ON ANY THEORY OF LIABILITY AND WHETHER OR
  NOT TI HAS BEEN ADVISED OF THE POSSIBILITY OF SUCH DAMAGES, ARISING IN ANY WAY
  OUT OF TI REFERENCE DESIGNS OR BUYER’S USE OF TI REFERENCE DESIGNS.
  TI reserves the right to make corrections, enhancements, improvements and other changes to its
  semiconductor products and services per JESD46, latest issue, and to discontinue any product or
  service per JESD48, latest issue. Buyers should obtain the latest relevant information before placing
  orders and should verify that such information is current and complete. All semiconductor products are
  sold subject to TI’s terms and conditions of sale supplied at the time of order acknowledgment.
  TI warrants performance of its components to the specifications applicable at the time of sale, in
  accordance with the warranty in TI’s terms and conditions of sale of semiconductor products.
  Testing and other quality control techniques for TI components are used to the extent TI deems
  necessary to support this warranty. Except where mandated by applicable law, testing of all
  parameters of each component is not necessarily performed.
- TI assumes no liability for applications assistance or the design of Buyers’ products. Buyers are
  responsible for their products and applications using TI components. To minimize the risks associated
  with Buyers’ products and applications, Buyers should provide adequate design and operating
  safeguards.
  Reproduction of significant portions of TI information in TI data books, data sheets or reference
  designs is permissible only if reproduction is without alteration and is accompanied by all associated
  warranties, conditions, limitations, and notices. TI is not responsible or liable for such altered
  documentation. Information of third parties may be subject to additional restrictions.
  Buyer acknowledges and agrees that it is solely responsible for compliance with all legal, regulatory
  and safety-related requirements concerning its products, and any use of TI components in its
  applications, notwithstanding any applications-related information or support that may be provided by
  TI. Buyer represents and agrees that it has all the necessary expertise to create and implement
  safeguards that anticipate dangerous failures, monitor failures and their consequences, lessen the
  likelihood of dangerous failures and take appropriate remedial actions. Buyer will fully indemnify TI
  and its representatives against any damages arising out of the use of any TI components in Buyer’s
  safety-critical applications.
  In some cases, TI components may be promoted specifically to facilitate safety-related
  applications. With such components, TI’s goal is to help enable customers to design and create their
  own end-product solutions that meet applicable functional safety standards and
  requirements. Nonetheless, such components are subject to these terms.
  TI has specifically designated certain components as meeting ISO/TS16949 requirements, mainly for
  automotive use. In any case of use of non-designated products, TI will not be responsible for any
  failure to meet ISO/TS16949 or use in automotive applications.
  No TI components are authorized for use in FDA Class III (or similar life-critical medical equipment)
  unless authorized officers of the parties have executed a written agreement specifically governing
  such use.
  Only those TI components that TI has specifically designated as military grade or “enhanced plastic”
  are designed and intended for use in military/aerospace applications or environments. Buyer
  acknowledges and agrees that any military or aerospace use of TI components that have not been so
  designated is solely at Buyer's risk, and Buyer is solely responsible for compliance with all legal and
  regulatory requirements in connection with such use.

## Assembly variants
001: not fitted C3 FID1 FID2 FID3 R3 R16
